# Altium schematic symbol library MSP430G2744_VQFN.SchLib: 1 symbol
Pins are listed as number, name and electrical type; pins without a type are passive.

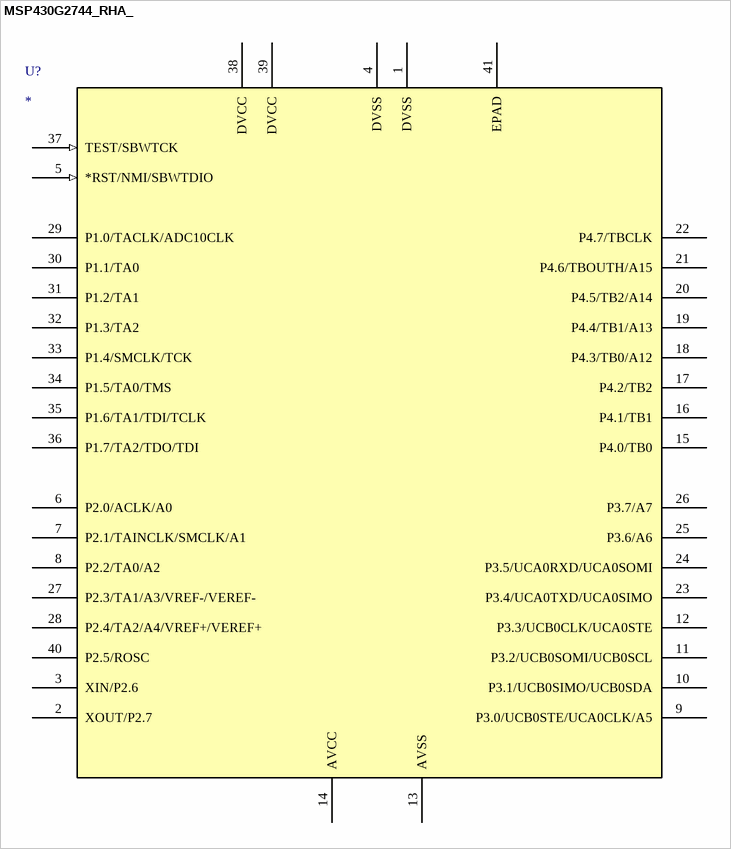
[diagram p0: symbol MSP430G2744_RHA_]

## MSP430G2744_RHA_
designator U?
Imported; Manufacturer_Part_Number: msp430g2744_rha_40; Vendor: TEXAS INSTRUMENTS
footprint RHA40_4P15X4P15
footprint QFN50P600X600X100-40N (QFN, 40-Leads, Body 6.2x6.2mm (max), Pitch 0.50mm, IPC Medium Density)
pins: 1 DVSS (power), 2 XOUT/P2.7, 3 XIN/P2.6, 4 DVSS (power), 5 *RST/NMI/SBWTDIO (in), 6 P2.0/ACLK/A0, 7 P2.1/TAINCLK/SMCLK/A1, 8 P2.2/TA0/A2, 9 P3.0/UCB0STE/UCA0CLK/A5, 10 P3.1/UCB0SIMO/UCB0SDA, 11 P3.2/UCB0SOMI/UCB0SCL, 12 P3.3/UCB0CLK/UCA0STE, 13 AVSS (power), 14 AVCC (power), 15 P4.0/TB0, 16 P4.1/TB1, 17 P4.2/TB2, 18 P4.3/TB0/A12, 19 P4.4/TB1/A13, 20 P4.5/TB2/A14, 21 P4.6/TBOUTH/A15, 22 P4.7/TBCLK, 23 P3.4/UCA0TXD/UCA0SIMO, 24 P3.5/UCA0RXD/UCA0SOMI, 25 P3.6/A6, 26 P3.7/A7, 27 P2.3/TA1/A3/VREF-/VEREF-, 28 P2.4/TA2/A4/VREF+/VEREF+, 29 P1.0/TACLK/ADC10CLK, 30 P1.1/TA0, 31 P1.2/TA1, 32 P1.3/TA2, 33 P1.4/SMCLK/TCK, 34 P1.5/TA0/TMS, 35 P1.6/TA1/TDI/TCLK, 36 P1.7/TA2/TDO/TDI, 37 TEST/SBWTCK (in), 38 DVCC (power), 39 DVCC (power), 40 P2.5/ROSC, 41 EPAD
